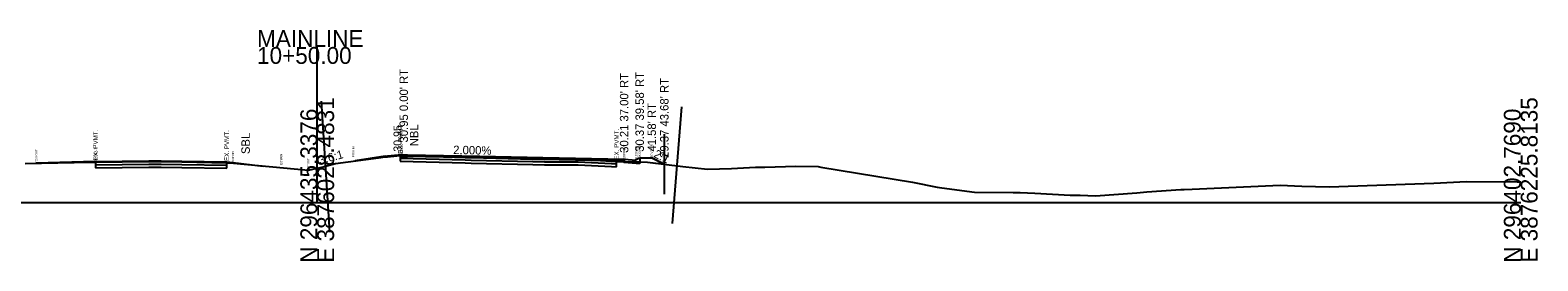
# Model space of a CAD drawing. Extents: x 14823 to 15251, y 114839 to 117377.
# Drawn here: x 15000.7 to 15251.2, y 115838.7 to 115877 of the extents above; entities that cross this region are included whole.
import ezdxf

# ---------------------------------------------------------------- set-up
doc = ezdxf.new("R2010")
doc.units = 0
for name, color, linetype in [('Default', 7, 'Continuous'), ('Level 1', 7, 'Continuous'), ('Level 10', 7, 'Continuous'), ('Level 11', 7, 'Continuous'), ('Level 2', 7, 'Continuous'), ('Level 25', 7, 'Continuous'), ('Level 3', 7, 'Continuous'), ('Level 4', 7, 'Continuous'), ('Level 42', 7, 'Continuous'), ('Level 49', 7, 'Continuous'), ('Level 50', 7, 'Continuous'), ('Level 52', 7, 'Continuous'), ('Level 53', 7, 'Continuous'), ('Level 56', 7, 'Continuous'), ('Level 59', 7, 'Continuous'), ('Level 63', 7, 'Continuous')]:
    doc.layers.add(name, color=color, linetype=linetype)

msp = doc.modelspace()

# ---------------------------------------------------------------- linework, layer by layer
at = {"layer": 'Default'}
for p, q in [((15049, 115865.23), (15050.42, 115843.45)), ((15108.87, 115864.24), (15107.34, 115844.87))]:
    msp.add_line(p, q, dxfattribs=at)
at = {"layer": 'Level 1'}
for p, q in [((14999.81, 115854.86), (15007.98, 115855.01)), ((15007.98, 115855.01), (15011.51, 115855.06)), ((15011.51, 115855.06), (15020.36, 115855.16)), ((15020.36, 115855.16), (15022.43, 115855.18)), ((15022.43, 115855.18), (15025.88, 115855.11)), ((15025.88, 115855.11), (15033.32, 115854.98)), ((15033.32, 115854.98), (15034.47, 115854.88)), ((15034.47, 115854.88), (15046.89, 115853.74)), ((15046.89, 115853.74), (15048.36, 115854.08)), ((15048.36, 115854.08), (15049.13, 115854.26)), ((15049.13, 115854.26), (15051.41, 115854.84)), ((15051.41, 115854.84), (15058.53, 115855.78)), ((15058.53, 115855.78), (15059.65, 115855.93)), ((15059.65, 115855.93), (15060.05, 115855.95)), ((15060.05, 115855.95), (15062.16, 115856.17)), ((15062.16, 115856.17), (15072.96, 115855.86)), ((15072.96, 115855.86), (15073.97, 115855.83)), ((15073.97, 115855.83), (15084.18, 115855.58)), ((15084.18, 115855.58), (15086.13, 115855.53)), ((15086.13, 115855.53), (15091.72, 115855.57)), ((15091.72, 115855.57), (15097.24, 115855.25)), ((15097.24, 115855.25), (15098.1, 115855.2)), ((15098.1, 115855.2), (15098.84, 115855.17)), ((15098.84, 115855.17), (15103.24, 115855.07)), ((15103.24, 115855.07), (15109.14, 115854.35)), ((15109.14, 115854.35), (15113.2, 115853.89)), ((15117.22, 115854.03), (15121.17, 115854.22)), ((15121.17, 115854.22), (15122.72, 115854.23)), ((15122.72, 115854.23), (15127.88, 115854.41)), ((15127.88, 115854.41), (15131.63, 115854.35)), ((15131.63, 115854.35), (15132.07, 115854.26)), ((15132.07, 115854.26), (15147.31, 115851.77)), ((15113.2, 115853.89), (15117.22, 115854.03)), ((15147.31, 115851.77), (15151.4, 115850.9)), ((15216.5, 115850.98), (15233.91, 115851.6)), ((15233.91, 115851.6), (15239.33, 115851.83)), ((15239.33, 115851.83), (15247.78, 115851.78)), ((15247.78, 115851.78), (15248.36, 115851.78)), ((15151.4, 115850.9), (15152.18, 115850.8)), ((15152.18, 115850.8), (15157.59, 115850.09)), ((15157.59, 115850.09), (15164.03, 115850.04)), ((15164.03, 115850.04), (15165.2, 115850.03)), ((15165.2, 115850.03), (15167.63, 115849.91)), ((15167.63, 115849.91), (15173.49, 115849.59)), ((15173.49, 115849.59), (15175.16, 115849.61)), ((15175.16, 115849.61), (15177.72, 115849.45)), ((15177.72, 115849.45), (15184.55, 115849.99)), ((15184.55, 115849.99), (15186.25, 115850.16)), ((15186.25, 115850.16), (15191.89, 115850.54)), ((15191.89, 115850.54), (15192.41, 115850.55)), ((15192.41, 115850.55), (15193.78, 115850.6)), ((15193.78, 115850.6), (15208.39, 115851.27)), ((15208.39, 115851.27), (15211.98, 115851.09)), ((15211.98, 115851.09), (15216.5, 115850.98))]:
    msp.add_line(p, q, dxfattribs=at)
at = {"layer": 'Level 10'}
for p, q in [((15034.36, 115855.01), (15034.36, 115854.89)), ((15062.37, 115856.19), (15062.37, 115856.31)), ((15062.37, 115856.02), (15062.37, 115856.19)), ((15062.37, 115856.19), (15063.36, 115856.17)), ((15062.37, 115856.02), (15063.36, 115856)), ((15075.36, 115855.93), (15063.36, 115856.17)), ((15075.36, 115855.76), (15063.36, 115856)), ((15085.86, 115855.72), (15075.36, 115855.93)), ((15085.86, 115855.55), (15075.36, 115855.76)), ((15085.86, 115855.72), (15099.36, 115855.45)), ((15085.86, 115855.55), (15099.36, 115855.28)), ((15099.36, 115855.45), (15099.36, 115855.57)), ((15099.36, 115855.28), (15099.36, 115855.45))]:
    msp.add_line(p, q, dxfattribs=at)
at = {"layer": 'Level 11'}
for p, q in [((15059.64, 115856.05), (15059.64, 115855.93)), ((15099.36, 115854.99), (15099.36, 115855.57)), ((15101.36, 115854.82), (15099.36, 115854.99)), ((15101.95, 115854.82), (15101.36, 115854.82)), ((15101.95, 115855.74), (15101.95, 115854.82))]:
    msp.add_line(p, q, dxfattribs=at)
at = {"layer": 'Level 2'}
for p, q in [((15011.51, 115855.19), (15001.68, 115854.89)), ((15011.51, 115855.19), (15020.36, 115855.29)), ((15020.36, 115855.29), (15022.43, 115855.3)), ((15022.43, 115855.3), (15025.88, 115855.24)), ((15025.88, 115855.24), (15033.32, 115855.11)), ((15033.33, 115855.11), (15034.36, 115855.01)), ((15059.64, 115856.05), (15060.05, 115856.07)), ((15062.37, 115856.31), (15060.04, 115856.07)), ((15062.37, 115856.31), (15063.36, 115856.29)), ((15063.36, 115856.29), (15075.36, 115856.05)), ((15075.36, 115856.05), (15085.86, 115855.84)), ((15085.86, 115855.84), (15099.36, 115855.57))]:
    msp.add_line(p, q, dxfattribs=at)
at = {"layer": 'Level 25'}
msp.add_line((15106.04, 115859.73), (15106.04, 115849.73), dxfattribs=at)
at = {"layer": 'Level 3'}
for p, q in [((15034.36, 115855.01), (15039.36, 115854.43)), ((15059.64, 115856.05), (15054.64, 115855.27)), ((15099.36, 115855.57), (15101.36, 115855.41)), ((15101.36, 115855.49), (15101.78, 115855.74)), ((15101.36, 115855.41), (15101.36, 115855.49)), ((15101.78, 115855.74), (15101.95, 115855.74))]:
    msp.add_line(p, q, dxfattribs=at)
at = {"layer": 'Level 4'}
for p, q in [((15101.95, 115855.74), (15103.95, 115855.78)), ((15103.95, 115855.78), (15106.04, 115854.73))]:
    msp.add_line(p, q, dxfattribs=at)
at = {"layer": 'Level 50'}
for points in [[(15062.37, 115856.31), (15063.36, 115856.29), (15075.36, 115856.05), (15085.86, 115855.84), (15099.36, 115855.57), (15099.36, 115855.16), (15098.84, 115855.17), (15098.1, 115855.2), (15097.24, 115855.25), (15091.72, 115855.57), (15086.13, 115855.53), (15084.18, 115855.58), (15073.97, 115855.83), (15072.96, 115855.86), (15062.16, 115856.17), (15060.05, 115855.95), (15059.65, 115855.93), (15058.53, 115855.78), (15054.64, 115855.27), (15059.64, 115856.05), (15060.04, 115856.07)], [(15062.37, 115856.31), (15063.36, 115856.29), (15075.36, 115856.05), (15085.86, 115855.84), (15099.36, 115855.57), (15099.36, 115855.16), (15098.84, 115855.17), (15098.1, 115855.2), (15097.24, 115855.25), (15091.72, 115855.57), (15086.13, 115855.53), (15084.18, 115855.58), (15073.97, 115855.83), (15072.96, 115855.86), (15062.16, 115856.17), (15060.05, 115855.95), (15059.65, 115855.93), (15058.53, 115855.78), (15054.64, 115855.27), (15059.64, 115856.05), (15060.04, 115856.07)], [(15101.95, 115854.82), (15101.36, 115854.82), (15099.36, 115854.99), (15099.36, 115855.16), (15101.95, 115855.1)], [(15101.95, 115854.82), (15101.36, 115854.82), (15099.36, 115854.99), (15099.36, 115855.16), (15101.95, 115855.1)], [(15101.95, 115855.1), (15103.24, 115855.07), (15106.04, 115854.73), (15103.95, 115855.78), (15101.95, 115855.74)], [(15101.95, 115855.1), (15103.24, 115855.07), (15106.04, 115854.73), (15103.95, 115855.78), (15101.95, 115855.74)]]:
    msp.add_lwpolyline(points, close=True, dxfattribs=at)
at = {"layer": 'Level 59'}
for p, q in [((15011.51, 115855.06), (15011.51, 115854.65)), ((15011.51, 115854.65), (15020.36, 115854.74)), ((15011.51, 115854.65), (15011.51, 115854.65)), ((15011.51, 115854.65), (15011.51, 115854.15)), ((15011.51, 115854.15), (15020.36, 115854.24)), ((15011.51, 115854.15), (15011.51, 115854.15)), ((15020.36, 115854.74), (15022.43, 115854.76)), ((15020.36, 115854.24), (15022.43, 115854.26)), ((15022.43, 115854.76), (15025.88, 115854.7)), ((15022.43, 115854.26), (15025.88, 115854.2)), ((15025.88, 115854.7), (15033.32, 115854.56)), ((15025.88, 115854.2), (15033.32, 115854.06)), ((15033.32, 115854.56), (15033.32, 115854.98)), ((15033.32, 115854.06), (15033.32, 115854.56)), ((15062.16, 115856.17), (15062.16, 115855.75)), ((15062.16, 115855.75), (15072.96, 115855.45)), ((15062.16, 115855.75), (15062.16, 115855.25)), ((15062.16, 115855.25), (15072.96, 115854.95)), ((15072.96, 115855.45), (15073.97, 115855.41)), ((15072.96, 115854.95), (15073.97, 115854.91)), ((15073.97, 115855.41), (15084.18, 115855.16)), ((15073.97, 115854.91), (15084.18, 115854.66)), ((15084.18, 115855.16), (15086.13, 115855.11)), ((15084.18, 115854.66), (15086.13, 115854.61)), ((15086.13, 115855.11), (15091.72, 115855.15)), ((15086.13, 115854.61), (15091.72, 115854.65)), ((15091.72, 115855.15), (15097.24, 115854.83)), ((15091.72, 115854.65), (15097.24, 115854.33)), ((15097.24, 115854.83), (15098.1, 115854.79)), ((15097.24, 115854.33), (15098.1, 115854.29)), ((15098.1, 115854.79), (15098.1, 115855.2)), ((15098.1, 115854.29), (15098.1, 115854.79))]:
    msp.add_line(p, q, dxfattribs=at)
at = {"layer": 'Level 63'}
for p, q in [((15048.36, 115848.36), (15048.36, 115874.2)), ((14848.36, 115848.36), (15048.36, 115848.36)), ((15048.36, 115848.36), (15248.36, 115848.36))]:
    msp.add_line(p, q, dxfattribs=at)

# ---------------------------------------------------------------- texts
at = {"layer": 'Level 42'}
for s, p in [('SBL', (15037.16, 115856.41)), ('NBL', (15065.16, 115857.71))]:
    msp.add_text(s, height=1.4, rotation=90, dxfattribs=at).set_placement(p)
at = {"layer": 'Level 49'}
msp.add_text('2.000%', height=1.4, rotation=358.8542, dxfattribs=at).set_placement((15070.95, 115856.42))
at = {"layer": 'Level 50'}
for s, rotation, p in [('3.6:1', 15.3812, (15048.81, 115854.67)), ('2:1', 333.435, (15104.17, 115855.98))]:
    msp.add_text(s, height=1.4, rotation=rotation, dxfattribs=at).set_placement(p)
at = {"layer": 'Level 52'}
for s, p in [("30.95 0.00' RT", (15063.44, 115858.34)), ("30.21 37.00' RT", (15100.06, 115856.62)), ("30.37 39.58' RT", (15102.65, 115856.79)), ("29.37 43.68' RT", (15106.74, 115855.78)), ("41.58' RT", (15104.65, 115856.83))]:
    msp.add_text(s, height=1.4, rotation=90, dxfattribs=at).set_placement(p)
at = {"layer": 'Level 53'}
for p in [(15011.89, 115855.06), (15033.7, 115854.98), (15062.54, 115856.17), (15098.48, 115855.2)]:
    msp.add_text(' EX. PVMT.', height=0.75, rotation=90, dxfattribs=at).set_placement(p)
at = {"layer": 'Level 56'}
for s, p in [('EOSLOUT', (15001.86, 115854.89)), ('EOPLOUT', (15011.69, 115855.19)), ('EOPRIN', (15034.54, 115855.01)), ('EOSLIN', (15054.55, 115855.91)), ('EOPLIN', (15062.55, 115856.31)), ('EOPROUT', (15099.54, 115855.57)), ('FLCURBR', (15101.54, 115855.49)), ('BKCURBR', (15102.12, 115855.74)), ('RCVRBLR', (15104.12, 115855.78)), ('FRDTCHR', (15106.22, 115854.73)), ('EOSRIN', (15042.54, 115854.61)), ('MEDDIT', (15047.07, 115853.86))]:
    msp.add_text(s, height=0.35, rotation=90, dxfattribs=at).set_placement(p)
at = {"layer": 'Level 63'}
for s, p in [('MAINLINE', (15038.37, 115874.2)), ('10+50.00', (15038.36, 115871.4))]:
    msp.add_text(s, height=2.8, dxfattribs=at).set_placement(p)
for s, height, p in [('E 3876028.4831', 2.8, (15051.16, 115838.36)), ('E 3876225.8135', 2.8, (15251.16, 115838.37)), ('N 296435.3376', 2.8, (15048.36, 115838.36)), ('N 296402.7690', 2.8, (15248.36, 115838.36)), (' 30.95', 1.32, (15062.36, 115856.31))]:
    msp.add_text(s, height=height, rotation=90, dxfattribs=at).set_placement(p)

doc.saveas('drawing.dxf')
